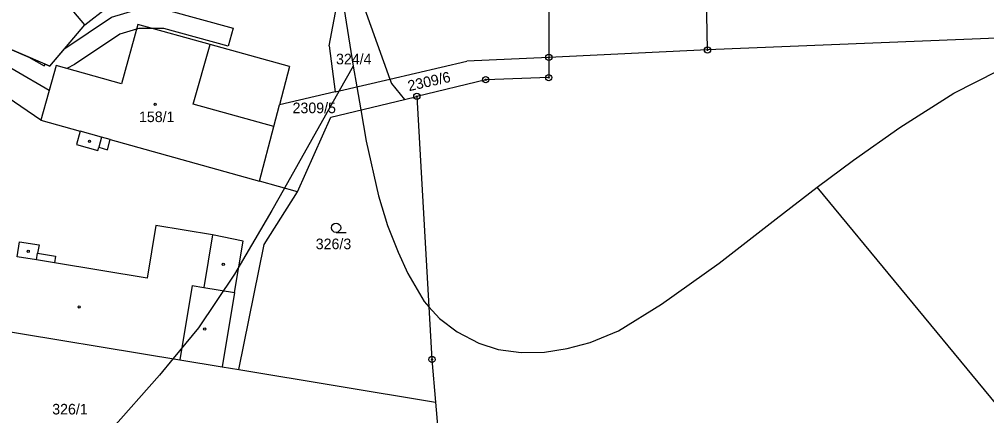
# Model space of a CAD drawing. Extents: x -546762 to -540209, y -1046851 to -1035694.
# Drawn here: x -542383.9 to -542228.7, y -1038969.2 to -1038905.5 of the extents above; entities that cross this region are included whole.
import ezdxf

# ---------------------------------------------------------------- set-up
doc = ezdxf.new("R2010")
doc.units = 0
for name, color, linetype in [('Vrstva 1', 7, 'Continuous'), ('Vrstva 18', 7, 'Continuous'), ('Vrstva 19', 7, 'Continuous'), ('Vrstva 24', 7, 'Continuous'), ('Vrstva 25', 7, 'Continuous'), ('Vrstva 3', 7, 'Continuous'), ('Vrstva 30', 7, 'Continuous'), ('Vrstva 37', 7, 'Continuous'), ('Vrstva 4', 7, 'Continuous'), ('Vrstva 52', 7, 'Continuous')]:
    doc.layers.add(name, color=color, linetype=linetype)

msp = doc.modelspace()

# ---------------------------------------------------------------- linework, layer by layer
at = {"layer": 'Vrstva 1'}
for p, q in [((-542273.49, -1038910.46), (-542273.83, -1038894.83)), ((-542348.67, -1038961.77), (-542317.12, -1038966.99))]:
    msp.add_line(p, q, dxfattribs=at)
for points in [[(-542298.87, -1038887.45), (-542298.95, -1038911.66)], [(-542334.18, -1038909.82), (-542330.4, -1038889.72)], [(-542330.4, -1038889.72), (-542329.46, -1038896), (-542328.49, -1038903.78), (-542324.44, -1038915.15)], [(-542373.37, -1038906.43), (-542362.65, -1038898.03)], [(-542373.37, -1038906.43), (-542375.16, -1038904.34)], [(-542378.96, -1038913.06), (-542373.37, -1038906.43)], [(-542364.85, -1038906.35), (-542367.51, -1038915.89)], [(-542353.29, -1038909.58), (-542364.85, -1038906.35)], [(-542219.13, -1038908.26), (-542273.49, -1038910.46)], [(-542378.96, -1038913.06), (-542388.99, -1038908.78)], [(-542340.54, -1038913.14), (-542353.29, -1038909.58)], [(-542334.18, -1038909.82), (-542333.23, -1038917.19)], [(-542298.95, -1038911.66), (-542312.1, -1038912.28)], [(-542298.95, -1038911.66), (-542298.96, -1038914.89)], [(-542273.49, -1038910.46), (-542298.95, -1038911.66)], [(-542377.96, -1038912.97), (-542380.41, -1038921.74)], [(-542367.51, -1038915.89), (-542377.96, -1038912.97)], [(-542340.54, -1038913.14), (-542342.14, -1038919.26)], [(-542324.44, -1038915.15), (-542312.1, -1038912.28)], [(-542380.41, -1038921.74), (-542392.29, -1038913.67)], [(-542333.23, -1038917.19), (-542324.44, -1038915.15)], [(-542324.44, -1038915.15), (-542324.2, -1038915.84), (-542322.08, -1038918.39)], [(-542309.07, -1038915.24), (-542320.12, -1038917.91)], [(-542298.96, -1038914.89), (-542309.07, -1038915.24)], [(-542333.23, -1038917.19), (-542342.14, -1038919.26)], [(-542343.06, -1038922.77), (-542342.14, -1038919.26)], [(-542333.93, -1038921.25), (-542322.08, -1038918.39)], [(-542322.08, -1038918.39), (-542320.12, -1038917.91)], [(-542320.12, -1038917.91), (-542317.7, -1038960.14)], [(-542339.28, -1038933.23), (-542333.93, -1038921.25)], [(-542345.35, -1038931.53), (-542343.06, -1038922.77)], [(-542339.28, -1038933.23), (-542345.35, -1038931.53)], [(-542344.63, -1038941.7), (-542339.28, -1038933.23)], [(-542348.67, -1038961.77), (-542344.63, -1038941.7)], [(-542389.9, -1038954.93), (-542358.14, -1038960.19)], [(-542358.14, -1038960.19), (-542351.33, -1038961.32)], [(-542351.33, -1038961.32), (-542348.67, -1038961.77)], [(-542317.7, -1038960.14), (-542317.12, -1038966.99)], [(-542317.12, -1038966.99), (-542314.95, -1038992.34)]]:
    msp.add_lwpolyline(points, dxfattribs=at)
at = {"layer": 'Vrstva 24'}
for centre, radius in [((-542273.49, -1038910.46), 0.5), ((-542298.95, -1038911.66), 0.5), ((-542298.95, -1038911.66), 0.1), ((-542273.49, -1038910.46), 0.1), ((-542309.07, -1038915.24), 0.5), ((-542298.96, -1038914.89), 0.5), ((-542309.07, -1038915.24), 0.1), ((-542298.96, -1038914.89), 0.1), ((-542320.12, -1038917.91), 0.5), ((-542320.12, -1038917.91), 0.1), ((-542317.7, -1038960.14), 0.5), ((-542317.7, -1038960.14), 0.1)]:
    msp.add_circle(centre, radius, dxfattribs=at)
at = {"layer": 'Vrstva 25'}
msp.add_line((-542333.08, -1038939.74), (-542331.48, -1038939.74), dxfattribs=at)
for centre, radius in [((-542362.08, -1038919.2), 0.175), ((-542372.63, -1038925.13), 0.175), ((-542333.08, -1038938.99), 0.75), ((-542382.45, -1038942.77), 0.175), ((-542351.16, -1038944.88), 0.175), ((-542374.28, -1038951.71), 0.175), ((-542354.14, -1038955.26), 0.175)]:
    msp.add_circle(centre, radius, dxfattribs=at)
at = {"layer": 'Vrstva 3'}
for points in [[(-542364.85, -1038906.35), (-542367.51, -1038915.89)], [(-542353.29, -1038909.58), (-542364.85, -1038906.35)], [(-542355.97, -1038919.16), (-542353.29, -1038909.58)], [(-542377.96, -1038912.97), (-542380.41, -1038921.74)], [(-542367.51, -1038915.89), (-542377.96, -1038912.97)], [(-542343.06, -1038922.77), (-542355.97, -1038919.16)], [(-542380.41, -1038921.74), (-542374.1, -1038923.5)], [(-542370.68, -1038924.46), (-542374.1, -1038923.5)], [(-542345.35, -1038931.53), (-542343.06, -1038922.77)], [(-542369.29, -1038924.85), (-542370.68, -1038924.46)], [(-542369.29, -1038924.85), (-542345.35, -1038931.53)]]:
    msp.add_lwpolyline(points, dxfattribs=at)
at = {"layer": 'Vrstva 30'}
msp.add_lwpolyline([(-542365.15, -1038904.02), (-542360.32, -1038904), (-542349.58, -1038906.96), (-542350.37, -1038909.85), (-542360.72, -1038907), (-542362.49, -1038907.01), (-542364.71, -1038907.02), (-542365.07, -1038907.13), (-542367.77, -1038907.94), (-542375.03, -1038912.82), (-542376.24, -1038913.45), (-542377.96, -1038912.97), (-542379.08, -1038916.97), (-542390.18, -1038910.54), (-542388.99, -1038908.78), (-542382.33, -1038911.62), (-542379.91, -1038913.02), (-542379.76, -1038912.72), (-542378.96, -1038913.06), (-542376.59, -1038910.25), (-542369.07, -1038905.2), (-542365.15, -1038904.02)], dxfattribs=at)
at = {"layer": 'Vrstva 37'}
msp.add_circle((-542362.08, -1038919.2), 0.175, dxfattribs=at)
at = {"layer": 'Vrstva 4'}
for points in [[(-542355.97, -1038919.16), (-542353.29, -1038909.58)], [(-542343.06, -1038922.77), (-542355.97, -1038919.16)], [(-542380.41, -1038921.74), (-542374.1, -1038923.5)], [(-542374.1, -1038923.5), (-542374.69, -1038925.62)], [(-542370.68, -1038924.46), (-542374.1, -1038923.5)], [(-542374.69, -1038925.62), (-542371.27, -1038926.58)], [(-542370.68, -1038924.46), (-542371.14, -1038926.09)], [(-542369.29, -1038924.85), (-542370.68, -1038924.46)], [(-542369.74, -1038926.48), (-542369.29, -1038924.85)], [(-542369.29, -1038924.85), (-542345.35, -1038931.53)], [(-542371.27, -1038926.58), (-542371.14, -1038926.09)], [(-542371.14, -1038926.09), (-542369.74, -1038926.48)], [(-542361.96, -1038938.63), (-542363.37, -1038947.11)], [(-542352.88, -1038940.13), (-542361.96, -1038938.63)], [(-542352.88, -1038940.13), (-542354.28, -1038948.57)], [(-542347.98, -1038941.15), (-542352.88, -1038940.13)], [(-542349.35, -1038949.39), (-542347.98, -1038941.15)], [(-542384.23, -1038943.65), (-542383.83, -1038941.24)], [(-542383.83, -1038941.24), (-542380.72, -1038941.75)], [(-542380.72, -1038941.75), (-542380.94, -1038943.08)], [(-542381.12, -1038944.17), (-542384.23, -1038943.65)], [(-542381.12, -1038944.17), (-542380.94, -1038943.08)], [(-542378.26, -1038944.64), (-542381.12, -1038944.17)], [(-542380.94, -1038943.08), (-542378.08, -1038943.56)], [(-542378.08, -1038943.56), (-542378.26, -1038944.64)], [(-542363.37, -1038947.11), (-542378.26, -1038944.64)], [(-542356.16, -1038948.26), (-542358.14, -1038960.19)], [(-542356.16, -1038948.26), (-542354.28, -1038948.57)], [(-542354.28, -1038948.57), (-542349.35, -1038949.39)], [(-542349.35, -1038949.39), (-542351.33, -1038961.32)]]:
    msp.add_lwpolyline(points, dxfattribs=at)
at = {"layer": 'Vrstva 52'}
for points in [[(-542335.15, -1038863.19), (-542334.72, -1038872.49), (-542334.49, -1038876.24), (-542333.97, -1038884.6), (-542333.81, -1038886.14), (-542332.42, -1038899.98), (-542332.38, -1038900.24), (-542330.33, -1038913.06)], [(-542255.93, -1038932.48), (-542250.1, -1038928.15), (-542242.63, -1038922.92), (-542233.97, -1038917.39), (-542223.36, -1038912.01), (-542222.9, -1038911.82), (-542213.18, -1038907.82), (-542212.46, -1038907.52), (-542203.05, -1038905.13), (-542191.85, -1038902.7), (-542177.47, -1038900.61), (-542164.92, -1038900.09), (-542151.59, -1038900.35), (-542148.82, -1038900.62), (-542140.77, -1038901.41), (-542135.65, -1038901.92), (-542133.83, -1038902.22), (-542119.7, -1038904.53), (-542117.27, -1038905.2), (-542101.67, -1038909.5)], [(-542330.33, -1038913.06), (-542332.56, -1038917.03), (-542341.34, -1038932.65), (-542343.36, -1038936.25), (-542349.37, -1038946.45), (-542355.12, -1038955.08), (-542359.2, -1038960.01), (-542361.4, -1038962.67), (-542369.24, -1038971.56), (-542375.25, -1038977.05), (-542377.53, -1038979.23), (-542379.82, -1038981.42), (-542382.61, -1038984.08)], [(-542330.33, -1038913.06), (-542329.75, -1038916.38), (-542329.11, -1038920.09), (-542328.24, -1038925.09), (-542326.28, -1038933.85), (-542324.83, -1038938.63), (-542323.12, -1038942.9), (-542321.58, -1038946.32), (-542318.94, -1038950.84), (-542318.19, -1038951.67), (-542316.46, -1038953.57), (-542313.65, -1038955.71), (-542310.15, -1038957.5), (-542307.07, -1038958.53)], [(-542307.07, -1038958.53), (-542303.4, -1038959.04), (-542299.65, -1038958.95), (-542295.98, -1038958.36), (-542292.31, -1038957.42), (-542287.78, -1038955.54), (-542280.87, -1038951.27), (-542271.65, -1038944.69), (-542262.5, -1038937.56), (-542255.93, -1038932.48)], [(-542168.66, -1039043.38), (-542178.1, -1039029.62), (-542188.82, -1039014.72), (-542195.26, -1039006.35), (-542197.77, -1039003.09), (-542199.28, -1039001.12), (-542212.87, -1038984.64), (-542229.08, -1038965.03), (-542255.93, -1038932.48)]]:
    msp.add_lwpolyline(points, dxfattribs=at)

# ---------------------------------------------------------------- texts
at = {"layer": 'Vrstva 18'}
for s, p in [('324/4', (-542333.08, -1038912.77)), ('2309/5', (-542340.05, -1038920.61)), ('326/3', (-542336.33, -1038942.44)), ('326/1', (-542378.6, -1038968.97))]:
    msp.add_text(s, height=1.7, dxfattribs=at).set_placement(p)
msp.add_text('2309/6', height=1.7, rotation=12.6943, dxfattribs=at).set_placement((-542321.36, -1038917.09))
at = {"layer": 'Vrstva 19'}
msp.add_text('158/1', height=1.7, dxfattribs=at).set_placement((-542364.68, -1038922.04))

doc.saveas('drawing.dxf')
